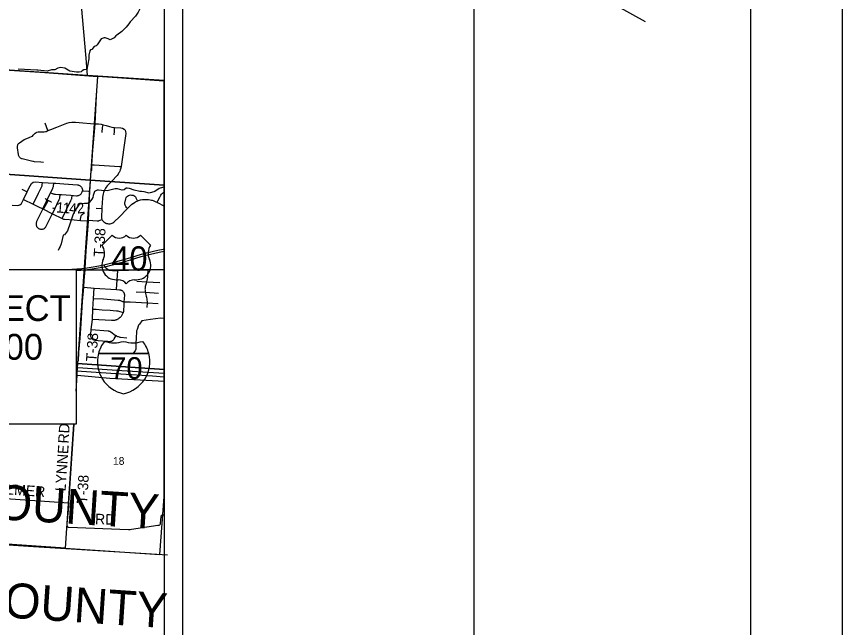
# Model space of a CAD drawing. Extents: x 0 to 34, y 0 to 26.1.
# Drawn here: x 29.516 to 34, y 17.45 to 20.765 of the extents above; entities that cross this region are included whole.
import ezdxf

# ---------------------------------------------------------------- set-up
doc = ezdxf.new("R2010")
doc.units = 0
for name, color, linetype in [('GM_X_County', 7, 'Continuous'), ('GM_X_County_Text', 7, 'Continuous'), ('GM_X_Interstate_Route', 7, 'Continuous'), ('GM_X_Interstate_Shield', 7, 'Continuous'), ('GM_X_Minor_River', 7, 'Continuous'), ('GM_X_Rail_Line', 7, 'Continuous'), ('GM_X_Section', 7, 'Continuous'), ('GM_X_Section_Text', 7, 'Continuous'), ('GM_X_Township_Road', 7, 'Continuous'), ('GM_X_Township_Road_Text', 7, 'Continuous'), ('GM_X_US_Route', 7, 'Continuous'), ('GM_X_US_Shield', 7, 'Continuous'), ('SC_Scratch1', 7, 'Continuous'), ('SH_Border', 7, 'Continuous'), ('SH_Cut_Line', 7, 'Continuous'), ('SH_Data', 7, 'Continuous'), ('SH_Text', 7, 'Continuous')]:
    doc.layers.add(name, color=color, linetype=linetype)

msp = doc.modelspace()

# ---------------------------------------------------------------- linework, layer by layer
at = {"layer": 'GM_X_County'}
msp.add_lwpolyline([(29.2794, 17.911), (29.6089, 17.8905), (29.7842, 17.8794), (30.3348, 17.8446)], dxfattribs=at)
at = {"layer": 'GM_X_Interstate_Route'}
for points in [[(29.8402, 18.8622), (29.8483, 18.8616), (30.0882, 18.8452), (30.2598, 18.8347), (30.3167, 18.8307)], [(29.8402, 18.8424), (29.8418, 18.8422), (30.0817, 18.8258), (30.2533, 18.8153), (30.3167, 18.8109)]]:
    msp.add_lwpolyline(points, dxfattribs=at)
at = {"layer": 'GM_X_Interstate_Shield'}
for p, q in [((29.9605, 18.9362), (30.2337, 18.9362)), ((30.2337, 18.9362), (29.9605, 18.9362)), ((30.2337, 18.9362), (29.9605, 18.9362))]:
    msp.add_line(p, q, dxfattribs=at)
for centre, start, end in [((30.1326, 18.8927), 141.669, 165.8066), ((30.0452, 19.1726), 253.0091, 286.9909), ((30.149, 19.1726), 253.0091, 286.9909), ((30.0616, 18.8927), 14.1934, 38.331), ((30.1326, 18.8927), 165.8066, 258.463), ((30.0616, 18.8927), 281.537, 14.1934)]:
    msp.add_arc(centre, 0.1776, start, end, dxfattribs=at)
at = {"layer": 'GM_X_Minor_River'}
for points in [[(30.2339, 20.9), (30.2206, 20.8867), (30.2032, 20.8716), (30.1971, 20.8621), (30.1899, 20.839), (30.1932, 20.8291), (30.1928, 20.82), (30.1898, 20.8143), (30.1769, 20.7897), (30.1624, 20.7677), (30.1325, 20.7362)], [(30.1325, 20.7362), (30.1264, 20.7256), (30.1112, 20.7074), (30.0881, 20.6843), (30.0611, 20.6635), (30.0558, 20.6609), (30.0467, 20.6499), (30.0247, 20.6382), (30.0134, 20.6435), (29.9975, 20.6493), (29.991, 20.6493), (29.9763, 20.6451), (29.9531, 20.6118), (29.9478, 20.6069), (29.9372, 20.6019), (29.9243, 20.5872), (29.9182, 20.5841), (29.9133, 20.5788), (29.9094, 20.5553), (29.9083, 20.5352), (29.8983, 20.4775), (29.8809, 20.4757), (29.8718, 20.4704), (29.8661, 20.4655), (29.8559, 20.4632), (29.8415, 20.4632), (29.8051, 20.4683), (29.7881, 20.4804), (29.779, 20.4846), (29.754, 20.4885), (29.7408, 20.4847), (29.7234, 20.4764), (29.7067, 20.4761), (29.6832, 20.4689), (29.6325, 20.474), (29.626, 20.4744), (29.5242, 20.4791)], [(30.1109, 19.834), (30.1003, 19.8257), (30.0901, 19.8227), (30.0636, 19.83), (30.0507, 19.8311), (30.0083, 19.8202), (29.9765, 19.8214), (29.961, 19.8234), (29.9542, 19.8223), (29.9398, 19.8162), (29.9318, 19.7942), (29.9298, 19.7836), (29.9253, 19.7741), (29.9108, 19.7555), (29.8987, 19.7514), (29.8858, 19.7503), (29.8779, 19.7499), (29.8612, 19.7496), (29.854, 19.7443), (29.8506, 19.7375), (29.8343, 19.7151), (29.8232, 19.6927), (29.8072, 19.6446), (29.7931, 19.6025), (29.7761, 19.5816), (29.77, 19.5782), (29.7585, 19.5323), (29.7521, 19.5168), (29.7483, 19.5077), (29.7426, 19.4963)], [(30.3167, 19.8414), (30.309, 19.8374), (30.2897, 19.8314), (30.2673, 19.8151), (30.2366, 19.806), (30.209, 19.8133), (30.195, 19.8152), (30.1848, 19.816), (30.1541, 19.8233), (30.1299, 19.8329), (30.1174, 19.8348), (30.1109, 19.834)], [(30.3167, 19.1271), (30.297, 19.1295), (30.2435, 19.1212), (30.1954, 19.1145), (30.1844, 19.0959), (30.1784, 19.0899), (30.1711, 19.0675), (30.1669, 19.0599), (30.1653, 19.0159), (30.1638, 18.9973), (30.1641, 18.9597), (30.1603, 18.9521), (30.1496, 18.9388)]]:
    msp.add_lwpolyline(points, dxfattribs=at)
at = {"layer": 'GM_X_Rail_Line'}
msp.add_lwpolyline([(29.8402, 19.3915), (29.853, 19.3917), (30.0851, 19.3917), (30.3167, 19.3952)], dxfattribs=at)
at = {"layer": 'GM_X_Section'}
for points in [[(28.9502, 20.5089), (29.1456, 20.4964), (29.1491, 20.4962), (29.6694, 20.4609), (29.9551, 20.4402), (29.9161, 19.8781), (29.4315, 19.9112), (28.9104, 19.9472)], [(30.3167, 19.8502), (30.3167, 20.415), (30.3157, 20.4151), (30.0618, 20.433), (29.9551, 20.4402), (29.9161, 19.8781)], [(30.3167, 18.85), (30.3167, 19.8502), (29.9161, 19.8781), (29.8466, 18.8822)]]:
    msp.add_lwpolyline(points, close=True, dxfattribs=at)
for points in [[(29.3959, 19.3933), (29.4315, 19.9112), (29.9161, 19.8781), (29.8466, 18.8822), (29.8402, 18.8827)], [(29.825, 18.5533), (29.7809, 17.8804), (30.2931, 17.847), (30.3167, 18.1593), (30.3167, 18.85), (29.8466, 18.8822), (29.8402, 18.7841)], [(29.8402, 18.8827), (29.8466, 18.8822), (29.8402, 18.7841)], [(29.825, 18.5533), (29.7809, 17.8804), (29.2811, 17.9144), (29.3334, 18.5533)]]:
    msp.add_lwpolyline(points, dxfattribs=at)
at = {"layer": 'GM_X_Township_Road'}
for p, q in [((29.9574, 20.4423), (29.9005, 20.446)), ((30.3167, 20.4176), (29.9574, 20.4423)), ((29.686, 20.1465), (29.6706, 20.1863)), ((29.5443, 19.8294), (29.5732, 19.8143)), ((29.9789, 19.7221), (29.9477, 19.724)), ((30.0588, 19.284), (30.0651, 19.388)), ((30.1691, 19.3293), (30.2222, 19.3262)), ((30.2222, 19.3262), (30.2947, 19.3217)), ((30.1661, 19.2723), (30.2148, 19.2695)), ((30.2148, 19.2695), (30.287, 19.265)), ((29.8402, 18.7324), (29.8456, 18.8196)), ((29.7996, 18.1265), (29.8286, 18.5533))]:
    msp.add_line(p, q, dxfattribs=at)
for points in [[(29.9005, 20.446), (29.8948, 20.5401), (29.8694, 20.8245), (29.8666, 20.8385), (29.8613, 20.8538), (29.8518, 20.8813), (29.8454, 20.9)], [(29.9005, 20.446), (29.3177, 20.4844), (28.111, 20.5622)], [(29.888, 19.3906), (29.8886, 19.4004), (29.8943, 19.4931), (29.899, 19.5606), (29.9041, 19.63), (29.906, 19.656), (29.9062, 19.6599), (29.9135, 19.8172), (29.9215, 19.9276), (29.924, 19.9309), (29.9257, 19.9531), (29.9257, 19.9615), (29.929, 20.0126), (29.9281, 20.0182), (29.9421, 20.1838), (29.9502, 20.3354), (29.9574, 20.4423)], [(29.5576, 20.0988), (29.5713, 20.1041), (29.5847, 20.1087), (29.588, 20.11), (29.5979, 20.1137), (29.6025, 20.1164), (29.6071, 20.1211), (29.6128, 20.128), (29.6174, 20.1326), (29.6219, 20.1359), (29.6265, 20.1377), (29.6333, 20.1391), (29.6436, 20.1393), (29.657, 20.14), (29.6669, 20.1405), (29.6728, 20.141), (29.6778, 20.1423), (29.686, 20.1465), (29.7021, 20.1522), (29.734, 20.1651), (29.7703, 20.1794), (29.7896, 20.1863), (29.8025, 20.1898), (29.817, 20.1917), (29.8366, 20.1917), (29.8751, 20.1882), (29.9181, 20.185), (29.9421, 20.1838)], [(29.9421, 20.1838), (29.9616, 20.1825), (29.9759, 20.1813), (29.9863, 20.1784), (30.0033, 20.1734), (30.021, 20.168), (30.0339, 20.1642), (30.0485, 20.1626), (30.0823, 20.1617), (30.0917, 20.1588), (30.0996, 20.1541), (30.1053, 20.1481), (30.1081, 20.1424), (30.1091, 20.1304), (30.1059, 20.1061), (30.0833, 19.9517), (30.0815, 19.9429), (30.0792, 19.934), (30.0762, 19.9258), (30.0725, 19.9187), (30.07, 19.9147), (30.0675, 19.9108), (30.0616, 19.9031), (30.0551, 19.8957), (30.0399, 19.8794), (30.0218, 19.8606), (30.0137, 19.8519), (30.0084, 19.8461), (30.0034, 19.8397), (29.9991, 19.8338), (29.9951, 19.8272), (29.9915, 19.8194), (29.9877, 19.8098), (29.986, 19.8029), (29.9845, 19.7948), (29.9841, 19.7908), (29.9836, 19.7869), (29.9834, 19.7796), (29.9815, 19.7543), (29.9799, 19.7297), (29.9789, 19.7221), (29.9783, 19.7129), (29.9768, 19.6883), (29.9766, 19.6822), (29.9768, 19.6782), (29.9779, 19.6724), (29.9798, 19.6646), (29.9809, 19.6623), (29.9833, 19.6584), (29.987, 19.6541), (29.9905, 19.6508), (29.9955, 19.6473), (30.0002, 19.6446), (30.0052, 19.6427), (30.0097, 19.6416), (30.015, 19.6409), (30.021, 19.6408), (30.0246, 19.6412), (30.0303, 19.6425), (30.0361, 19.6447), (30.0394, 19.6464), (30.0446, 19.6497), (30.0468, 19.6517), (30.0499, 19.6547), (30.071, 19.6749), (30.1183, 19.7238), (30.1256, 19.731), (30.1336, 19.7388), (30.1404, 19.7448), (30.1479, 19.7506), (30.1491, 19.7515), (30.1563, 19.7565), (30.1612, 19.7591), (30.1661, 19.7618), (30.171, 19.7639), (30.1777, 19.7669), (30.189, 19.7699), (30.1994, 19.7719), (30.2021, 19.7722), (30.2112, 19.7732), (30.2166, 19.7734), (30.2234, 19.7732), (30.2317, 19.7726), (30.2419, 19.7712), (30.2494, 19.7695), (30.2526, 19.7685), (30.2586, 19.7666), (30.2731, 19.7606), (30.2796, 19.7578), (30.2853, 19.7546), (30.3123, 19.7396), (30.3167, 19.7375)], [(29.9815, 20.1355), (29.9831, 20.1636), (29.9863, 20.1784)], [(30.0466, 20.1235), (30.0476, 20.1423), (30.0485, 20.1626)], [(29.6632, 19.9739), (29.6483, 19.975), (29.6127, 19.9774), (29.6082, 19.9779), (29.6038, 19.9788), (29.5475, 19.9927), (29.5439, 19.9938), (29.5406, 19.9954), (29.5374, 19.9974), (29.5345, 19.9999), (29.532, 20.0026), (29.5299, 20.0057), (29.5282, 20.0091), (29.527, 20.0126), (29.5262, 20.0162), (29.5208, 20.0537), (29.5206, 20.0572), (29.5207, 20.0606), (29.5212, 20.064), (29.5222, 20.0673), (29.5236, 20.0705), (29.5253, 20.0735), (29.5274, 20.0762), (29.5298, 20.0787), (29.5325, 20.0809), (29.5576, 20.0988)], [(29.9257, 19.9615), (29.9368, 19.9605), (30.0745, 19.9518), (30.0833, 19.9517)], [(29.4925, 19.742), (29.5233, 19.7402), (29.5281, 19.7412), (29.5339, 19.7443), (29.5428, 19.7514), (29.554, 19.7729), (29.5732, 19.8143), (29.5819, 19.8343), (29.5965, 19.8592), (29.6059, 19.8659), (29.6198, 19.8678), (29.6566, 19.8648), (29.7183, 19.8611), (29.724, 19.8607), (29.7289, 19.8605), (29.7726, 19.8572), (29.8471, 19.8517), (29.8498, 19.8513), (29.8516, 19.851), (29.8547, 19.8499), (29.8576, 19.8487), (29.8606, 19.8469), (29.8634, 19.8449), (29.8666, 19.8416), (29.8689, 19.8386), (29.8708, 19.8353), (29.8724, 19.8312), (29.8735, 19.8269), (29.8739, 19.8202), (29.8787, 19.8199), (29.9075, 19.8175), (29.9135, 19.8172)], [(29.6058, 19.7474), (29.6349, 19.8077), (29.6544, 19.8471), (29.6558, 19.8522), (29.6566, 19.8648)], [(29.6581, 19.722), (29.6976, 19.8019), (29.701, 19.8094), (29.7043, 19.8158), (29.7124, 19.8318), (29.7139, 19.8352), (29.7153, 19.8391), (29.7162, 19.8423), (29.7168, 19.8452), (29.7173, 19.8486), (29.7176, 19.8522), (29.718, 19.8556), (29.7183, 19.8611)], [(29.701, 19.8094), (29.7058, 19.807), (29.7087, 19.8055), (29.7114, 19.8044), (29.7145, 19.8032), (29.7183, 19.8024), (29.7227, 19.8019), (29.7273, 19.8017), (29.7454, 19.8003), (29.7528, 19.7997), (29.76, 19.7992), (29.8104, 19.7955), (29.818, 19.7949), (29.8253, 19.7944), (29.8414, 19.7932), (29.8454, 19.7931), (29.8493, 19.7934), (29.8526, 19.7942), (29.8565, 19.7956), (29.8602, 19.7975), (29.8637, 19.8003), (29.8664, 19.8029), (29.8686, 19.806), (29.8709, 19.8099), (29.8724, 19.8136), (29.8739, 19.8202)], [(29.7109, 19.6956), (29.748, 19.7717), (29.7501, 19.7761), (29.7511, 19.78), (29.7516, 19.783), (29.7519, 19.7856), (29.7524, 19.794), (29.7528, 19.7997)], [(29.7633, 19.6693), (29.8116, 19.7676), (29.8132, 19.7709), (29.8147, 19.7743), (29.8157, 19.777), (29.8166, 19.7806), (29.8171, 19.7839), (29.8176, 19.79), (29.818, 19.7949)], [(30.1183, 19.7238), (30.1129, 19.7293), (30.1092, 19.7337), (30.1067, 19.7375), (30.1049, 19.742), (30.1038, 19.7469), (30.1037, 19.7524), (30.109, 19.7766), (30.1109, 19.7825), (30.1139, 19.7871), (30.1181, 19.7908), (30.1233, 19.7941), (30.1293, 19.7964), (30.1346, 19.797), (30.1402, 19.7967), (30.1484, 19.7953), (30.1532, 19.7936), (30.1578, 19.7904), (30.1615, 19.7861), (30.1629, 19.7839), (30.1644, 19.7817), (30.1688, 19.7706), (30.171, 19.7639)], [(30.2796, 19.7578), (30.2829, 19.7656), (30.2936, 19.7844), (30.2995, 19.7953), (30.3033, 19.8007), (30.3081, 19.806), (30.3133, 19.8102), (30.3167, 19.8122)], [(29.554, 19.7729), (29.6058, 19.7474), (29.6311, 19.7352), (29.6581, 19.722), (29.7109, 19.6956), (29.7633, 19.6693), (29.7707, 19.6666), (29.7772, 19.6654), (29.8298, 19.6617)], [(29.6581, 19.722), (29.6555, 19.7151), (29.6251, 19.6533), (29.6237, 19.6501), (29.6228, 19.6468), (29.6222, 19.6433), (29.622, 19.6399), (29.6223, 19.6364), (29.623, 19.633), (29.624, 19.6296), (29.6249, 19.6268), (29.6269, 19.6236), (29.6293, 19.6207), (29.6321, 19.6181), (29.6351, 19.6159), (29.6384, 19.614), (29.6419, 19.6127), (29.6456, 19.6118), (29.6494, 19.6113), (29.653, 19.6112), (29.6568, 19.6116), (29.6605, 19.6126), (29.6641, 19.6141), (29.6674, 19.616), (29.6704, 19.6183), (29.6731, 19.6209), (29.6756, 19.6243), (29.6774, 19.6275), (29.708, 19.6889), (29.7109, 19.6956)], [(29.8634, 19.6593), (29.8639, 19.6693), (29.8642, 19.6735), (29.8648, 19.6784), (29.8662, 19.6825), (29.8693, 19.6873), (29.873, 19.6918), (29.8847, 19.7019)], [(29.8298, 19.6617), (29.8634, 19.6593), (29.906, 19.656)], [(29.9062, 19.6599), (29.9543, 19.6569), (29.9572, 19.6569), (29.9595, 19.657), (29.9622, 19.6574), (29.9649, 19.6582), (29.9693, 19.6595), (29.9747, 19.662), (29.9798, 19.6646)], [(29.9894, 19.4183), (29.9951, 19.408), (30.0027, 19.4002), (30.0113, 19.3941), (30.0193, 19.39), (30.0259, 19.3884), (30.0378, 19.3877), (30.0651, 19.388), (30.1243, 19.3897), (30.2291, 19.3918), (30.3167, 19.3934)], [(29.852, 18.8955), (29.8551, 18.9439), (29.8607, 19.0208), (29.8667, 19.1002), (29.8706, 19.1571), (29.8749, 19.2198), (29.8808, 19.2963), (29.883, 19.3338), (29.888, 19.3906)], [(30.2291, 19.3918), (30.2275, 19.3624), (30.2269, 19.3514), (30.2258, 19.3428), (30.2222, 19.3262), (30.219, 19.3169), (30.2171, 19.3107), (30.216, 19.3064), (30.2149, 19.3011), (30.2142, 19.2965), (30.2136, 19.2903), (30.2134, 19.2855), (30.2136, 19.2823), (30.2138, 19.2772), (30.2148, 19.2695), (30.2155, 19.267), (30.2163, 19.2626), (30.2202, 19.2481), (30.2215, 19.2426), (30.2238, 19.2316), (30.2243, 19.2265), (30.2247, 19.2192), (30.2245, 19.2117), (30.223, 19.186)], [(29.8808, 19.2963), (29.938, 19.292), (30.0588, 19.284), (30.0749, 19.283), (30.0768, 19.2828), (30.0789, 19.2824), (30.0814, 19.2818), (30.0828, 19.2814), (30.0839, 19.2809), (30.0858, 19.28), (30.0871, 19.2793), (30.0888, 19.2783), (30.0906, 19.2769), (30.0925, 19.2754), (30.0955, 19.2721), (30.0963, 19.271), (30.0969, 19.27), (30.0976, 19.2689), (30.0984, 19.2675), (30.0991, 19.2659), (30.0996, 19.2646), (30.1002, 19.263), (30.1006, 19.2615), (30.1009, 19.2601), (30.1011, 19.2585), (30.1013, 19.2566), (30.1014, 19.2548), (30.1013, 19.2527), (30.0992, 19.2179), (30.0981, 19.1954), (30.0969, 19.1747), (30.0971, 19.1668), (30.0965, 19.1638), (30.0956, 19.1599), (30.095, 19.1575), (30.0936, 19.1536), (30.0917, 19.1517), (30.0902, 19.1484), (30.0883, 19.1448), (30.0865, 19.1421), (30.0839, 19.1385), (30.0807, 19.1349), (30.078, 19.1321), (30.074, 19.1284), (30.0719, 19.1268), (30.0697, 19.1255), (30.0665, 19.1235), (30.0622, 19.1211), (30.0598, 19.1201), (30.0577, 19.1193), (30.0556, 19.1184), (30.0537, 19.1178), (30.0511, 19.1171), (30.0487, 19.1166), (30.0462, 19.1161), (30.0438, 19.1157), (30.042, 19.1155), (30.0399, 19.1153), (30.0379, 19.1152), (30.0321, 19.1153), (29.9967, 19.1177), (29.9276, 19.1219)], [(29.925, 19.0193), (29.9234, 19.0212), (29.922, 19.0234), (29.9205, 19.0263), (29.9196, 19.0287), (29.9189, 19.0313), (29.9184, 19.0338), (29.9182, 19.0363), (29.9184, 19.0383), (29.9185, 19.0405), (29.9205, 19.0675), (29.9276, 19.1219), (29.9308, 19.178), (29.9344, 19.2347), (29.938, 19.292)], [(29.9344, 19.2347), (29.9879, 19.2329), (30.0682, 19.2272), (30.0699, 19.2271), (30.0711, 19.2269), (30.0721, 19.2267), (30.0735, 19.2264), (30.0749, 19.226), (30.0767, 19.2254), (30.0806, 19.2237), (30.0873, 19.2211), (30.0907, 19.2198), (30.0932, 19.219), (30.0947, 19.2186), (30.0958, 19.2184), (30.0992, 19.2179), (30.1333, 19.2167), (30.2245, 19.2117), (30.2853, 19.208)], [(29.9308, 19.178), (29.9487, 19.1768), (29.9803, 19.1747), (30.0238, 19.1715), (30.0406, 19.1705), (30.0583, 19.1693), (30.0656, 19.1678), (30.0956, 19.1599)], [(29.9205, 19.0675), (30.0127, 19.0597), (30.0152, 19.0595), (30.0176, 19.0589), (30.0198, 19.0582), (30.0218, 19.0575), (30.0238, 19.0564), (30.0256, 19.0554), (30.0272, 19.0543), (30.0519, 19.0366), (30.0541, 19.0351), (30.0561, 19.0338), (30.0599, 19.0316), (30.0641, 19.0297), (30.068, 19.0283), (30.0723, 19.027), (30.0765, 19.026), (30.078, 19.0258), (30.081, 19.0254), (30.1152, 19.0227)], [(29.925, 19.0193), (29.9292, 19.015), (29.9309, 19.0138), (29.933, 19.0125), (29.9355, 19.0113), (29.9384, 19.0102), (29.9412, 19.0094), (29.9441, 19.009), (29.9589, 19.0078), (29.9822, 19.0056), (30.0098, 19.0031), (30.0152, 19.0026), (30.0189, 19.0024), (30.0215, 19.0023), (30.024, 19.0025), (30.0263, 19.0027), (30.0284, 19.0032), (30.0307, 19.0039), (30.0326, 19.0046), (30.0343, 19.0053), (30.0365, 19.0067), (30.0383, 19.0079), (30.0399, 19.0091), (30.0418, 19.0112), (30.0438, 19.0136), (30.0459, 19.0169), (30.0561, 19.0338)], [(29.8456, 18.8196), (30.0231, 18.8029), (30.3167, 18.7874)], [(29.297, 18.1618), (29.7996, 18.1265), (29.7888, 18.0131), (29.7889, 18.0047), (29.79, 18.0009), (29.7912, 17.9975), (29.7931, 17.9956), (29.7961, 17.9941), (29.8003, 17.9941), (30.1245, 17.9826), (30.1325, 17.9823), (30.1405, 17.9831), (30.2835, 18.005), (30.2896, 18.0054), (30.2937, 18.0065), (30.2956, 18.0084), (30.2975, 18.0126), (30.2979, 18.016), (30.3011, 18.0533), (30.3022, 18.0567), (30.3034, 18.059), (30.3053, 18.0602), (30.3068, 18.0613), (30.3102, 18.0609), (30.3167, 18.062)]]:
    msp.add_lwpolyline(points, dxfattribs=at)
at = {"layer": 'GM_X_US_Route'}
for points in [[(29.8047, 19.3933), (29.8158, 19.3937), (29.8429, 19.3956), (29.8701, 19.3982), (29.8886, 19.4004), (29.9096, 19.4032), (29.9312, 19.4068), (29.9634, 19.4126), (29.9894, 19.4183), (30.0184, 19.425), (30.0408, 19.4312), (30.0855, 19.4438), (30.1361, 19.4585), (30.1947, 19.4756), (30.2217, 19.4832), (30.2444, 19.4889), (30.2675, 19.4944), (30.2918, 19.4997), (30.3142, 19.5039), (30.3167, 19.5043)], [(29.9951, 19.408), (30.0371, 19.4179), (30.0841, 19.4311), (30.1347, 19.4458), (30.1935, 19.4629), (30.2202, 19.4704), (30.2431, 19.4763), (30.266, 19.4818), (30.2904, 19.4876), (30.3167, 19.4921)], [(29.8402, 19.3866), (29.8424, 19.3867), (29.888, 19.3906), (29.9137, 19.3939), (29.9369, 19.3975), (29.9693, 19.4029), (29.9951, 19.408)]]:
    msp.add_lwpolyline(points, dxfattribs=at)
at = {"layer": 'GM_X_US_Shield'}
for p, q in [((30.035, 19.5788), (29.9801, 19.5239)), ((30.2438, 19.5239), (30.1888, 19.5788)), ((30.057, 19.3371), (30.068, 19.3371)), ((30.1559, 19.3371), (30.1669, 19.3371))]:
    msp.add_line(p, q, dxfattribs=at)
for centre, radius, start, end in [((30.0735, 19.618), 0.0549, 225.573, 314.427), ((30.1504, 19.618), 0.0549, 225.573, 314.427), ((29.9171, 19.4798), 0.0769, 334.5471, 35.0009), ((30.3068, 19.4798), 0.0769, 144.9991, 205.4529), ((30.0561, 19.414), 0.0769, 154.8319, 270.6383), ((30.1677, 19.414), 0.0769, 269.3617, 25.1681), ((30.068, 19.2822), 0.0549, 36.8699, 90), ((30.1559, 19.2822), 0.0549, 90, 143.1301)]:
    msp.add_arc(centre, radius, start, end, dxfattribs=at)
at = {"layer": 'SC_Scratch1'}
msp.add_line((32.9305, 20.7362), (23.2874, 26.1047), dxfattribs=at)
at = {"layer": 'SH_Border'}
msp.add_line((32, 0.5), (32, 21.5), dxfattribs=at)
msp.add_lwpolyline([(1.5, 21.5), (33.5, 21.5), (33.5, 0.5), (1.5, 0.5)], close=True, dxfattribs=at)
at = {"layer": 'SH_Cut_Line'}
msp.add_lwpolyline([(0, 0), (34, 0), (34, 22), (0, 22)], close=True, dxfattribs=at)
at = {"layer": 'SH_Data'}
for points in [[(23.4167, 21), (30.4167, 21), (30.4167, 14), (23.4167, 14)], [(23.5167, 20.9), (30.3167, 20.9), (30.3167, 14.1), (23.5167, 14.1)], [(28.1615, 19.3933), (29.8402, 19.3933), (29.8402, 18.5533), (28.1615, 18.5533)]]:
    msp.add_lwpolyline(points, close=True, dxfattribs=at)

# ---------------------------------------------------------------- texts
at = {"layer": 'GM_X_County_Text'}
for s, rotation, p in [('LICKING COUNTY', 356.3996, (28.1352, 18.1183)), ('FAIRFIELD COUNTY', 356.1646, (27.8997, 17.6092))]:
    msp.add_text(s, height=0.189394, rotation=rotation, dxfattribs=at).set_placement(p)
at = {"layer": 'GM_X_Interstate_Shield'}
msp.add_text('70', height=0.11837, dxfattribs=at).set_placement((30.0243, 18.7986))
at = {"layer": 'GM_X_Section_Text'}
msp.add_text('18', height=0.04186, rotation=0, dxfattribs=at).set_placement((30.0396, 18.3329))
at = {"layer": 'GM_X_Township_Road_Text'}
for s, height, rotation, p in [('T', 0.0568, 330.9887, (29.6422, 19.7319)), ('1', 0.0568, 355.64, (29.7292, 19.7025)), ('1', 0.0568, 355.8766, (29.7643, 19.6998)), ('4', 0.0568, 356.875, (29.8003, 19.6972)), ('2', 0.0568, 6.6516, (29.8458, 19.6956)), ('-', 0.0568, 357.1196, (29.7063, 19.7036)), ('T-38', 0.05682, 86.8206, (29.991, 19.4598)), ('T-38', 0.05682, 86.091, (29.9493, 18.8911)), ('RD', 0.05682, 86.5467, (29.7982, 18.4474)), ('LYNNE', 0.05682, 86.1316, (29.7821, 18.1876)), ('T-38', 0.05682, 86.4464, (29.8993, 18.1209)), ('PALMER', 0.05682, 355.9261, (29.3582, 18.1802)), ('RD', 0.05682, 358.0262, (29.9416, 18.0111))]:
    msp.add_text(s, height=height, rotation=rotation, dxfattribs=at).set_placement(p)
at = {"layer": 'GM_X_US_Shield'}
msp.add_text('40', height=0.13184, dxfattribs=at).set_placement((30.031, 19.3866))
at = {"layer": 'SH_Text'}
for s, p in [('BEGIN PROJECT', (28.3015, 19.1133)), ('STA. 560+00.00', (28.3015, 18.9033))]:
    msp.add_text(s, height=0.14, dxfattribs=at).set_placement(p)

doc.saveas('drawing.dxf')
